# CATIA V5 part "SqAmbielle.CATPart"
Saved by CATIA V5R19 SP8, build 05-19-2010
Part number: SqAmbielle
Publications: "Droite.1", "Plan.1"
Bounding box of the stored display mesh (mm): x 0 to 20, y 0 to 285, z 0 to 0
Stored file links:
  F:\Travail\2e année\IAO\Projetsave\SqAmbielle.CATPart
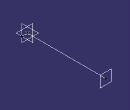
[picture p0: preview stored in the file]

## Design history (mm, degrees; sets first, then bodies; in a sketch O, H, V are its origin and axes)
Set1
  Point1: (0, 0, 0)
  Plane1: type Offset, RefPlane zx-plane, Offset 285
  Line1: type PtDir, RefPoint Point1, Direction yz-plane, Start 0, End 20
  Line2: type PtDir, RefPoint Point1, Direction zx-plane, Start 0, End 285
Body1 (main body)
